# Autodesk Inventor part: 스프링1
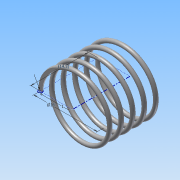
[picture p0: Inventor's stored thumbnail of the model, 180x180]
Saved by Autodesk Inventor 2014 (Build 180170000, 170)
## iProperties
Created: 2015-06
Part Number: 스프링1
Material: 강철, 연강
Document SubType Name: Modeling
Designer: Administrator
Density: 7.86 g/cm^3
Appearance: 강철
Mass: 1.52996 g
Surface Area: 7.87153 cm^2
Volume: 0.194652 cm^3
Author: Administrator
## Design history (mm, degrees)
sketch "스케치1"
  geometry: L1 (0, 0)-(-8, 0); L2 (-8, 0)-(-8, 14.5); L3 (-8, 14.5)-(0, 14.5); L4 (0, 14.5)-(0, 0); C1 r 0.5 at (-8, 0)
  constraints: 8 end point, 2 parallel, 1 centre point, 1 coincident, 1 horizontal, 1 perpendicular
  dimensions: "d0" = 1 diameter of C1; "d1" = 16 diameter of L2 L4; "d2" = 14.5 distance of L1.end L2.end (derived)
feature "코일1" sketch "스케치1" pitch "d3" = 10; turns "d5" = 5; dims "d4" = 14.5 (= d2), "d6" = 0, angle "d7" = 90 deg, angle "d8" = 90 deg, "d9" = 0, "d10" = 0
sketch "스케치2"
  geometry: L1 (8.5, 0)-(7.5, 0) reference; 1 further point
  constraints: 1 horizontal alignment
extrude "돌출1" cut sketch "스케치2" stored distance "d11" = 10; taper "d12" = 0 deg
node "작업 평면1"
sketch "스케치3"
  geometry: L1 (7.5, 0)-(8.5, 0) reference; 1 further point
  constraints: 1 horizontal alignment
extrude "돌출2" cut sketch "스케치3" stored distance "d14" = 10; taper "d15" = 0 deg
node "솔리드1"
node "절단 모서리 투영1"
node "절단 모서리 투영2"
other parameters: "d13" = 14.5 (= d2)
